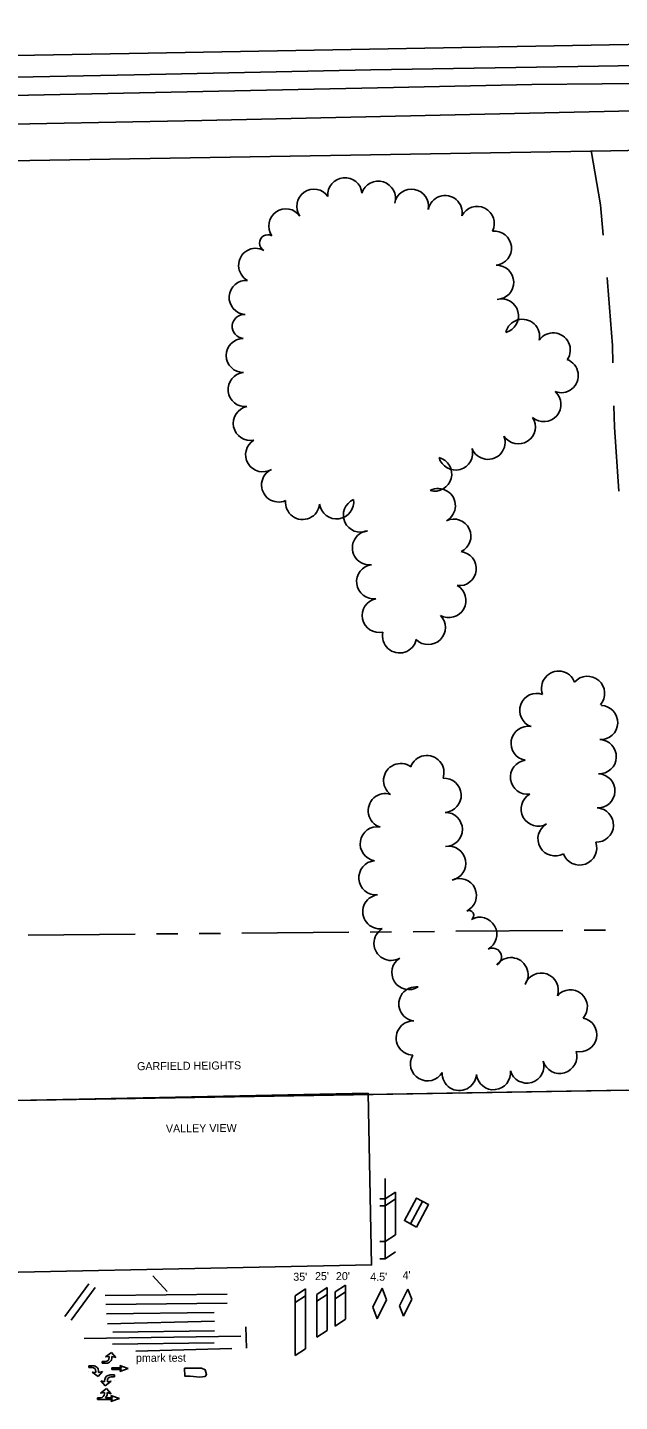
# Model space of a CAD drawing. Extents: x -2233 to 187241, y 4582 to 150524.
# Drawn here: x 103255 to 103601, y 58619 to 59422 of the extents above; entities that cross this region are included whole.
import ezdxf

# ---------------------------------------------------------------- set-up
doc = ezdxf.new("R2010")
doc.units = 0
for name, color, linetype in [('BLDG', 7, 'Continuous'), ('DIVISIONS', 7, 'Continuous'), ('DRIVWY', 7, 'Continuous'), ('DV_X_Corp_Line', 7, 'Continuous'), ('GE_X_CL_2000', 7, 'Continuous'), ('PM_P_Cells', 7, 'Continuous'), ('PM_P_Channelizing_Line', 7, 'Continuous'), ('PM_P_CL_Dashed', 7, 'Continuous'), ('PM_P_CL_Double_Solid', 7, 'Continuous'), ('PM_P_CL_Pass_Proh_Lt', 7, 'Continuous'), ('PM_P_CL_Pass_Proh_Rt', 7, 'Continuous'), ('PM_P_Crosswalk', 7, 'Continuous'), ('PM_P_Edge_Line', 7, 'Continuous'), ('PM_P_Island', 7, 'Continuous'), ('PM_P_Lane_Line', 7, 'Continuous'), ('PM_P_Stop_Line', 7, 'Continuous'), ('PM_P_Text', 7, 'Continuous'), ('PM_P_Transverse_Line', 7, 'Continuous'), ('ROAD', 7, 'Continuous'), ('RW_X_Fee_RW', 7, 'Continuous'), ('SG_P_Detection', 7, 'Continuous'), ('TREES', 7, 'Continuous')]:
    doc.layers.add(name, color=color, linetype=linetype)

msp = doc.modelspace()

# ---------------------------------------------------------------- linework, layer by layer
at = {"layer": 'BLDG'}
msp.add_lwpolyline([(103153.42, 58792.9), (103453.99, 58799.02), (103456.04, 58698.72), (103155.45, 58692.59)], close=True, dxfattribs=at)
at = {"layer": 'DIVISIONS'}
for p, q in [((103317.76, 58892.09), (103255.26, 58891.54)), ((103342.76, 58892.3), (103330.26, 58892.19)), ((103367.76, 58892.52), (103355.26, 58892.41)), ((103442.75, 58893.18), (103380.26, 58892.63)), ((103467.75, 58893.39), (103455.25, 58893.29)), ((103492.75, 58893.61), (103480.25, 58893.5)), ((103567.75, 58894.27), (103505.25, 58893.72)), ((103592.75, 58894.49), (103580.25, 58894.38))]:
    msp.add_line(p, q, dxfattribs=at)
at = {"layer": 'DRIVWY'}
for points in [[(103584.47, 59350.22), (103589.9, 59318.4), (103591.47, 59300.75)], [(103593.7, 59275.85), (103593.94, 59273.17), (103596.9, 59236.13), (103597.11, 59225.98)], [(103597.66, 59200.99), (103597.94, 59188.42), (103600.63, 59151.08)]]:
    msp.add_lwpolyline(points, dxfattribs=at)
at = {"layer": 'DV_X_Corp_Line'}
for p, q in [((103605.04, 58800.91), (103465.01, 58798.49)), ((103605.04, 58800.91), (103465.01, 58798.49)), ((103465.01, 58798.49), (103605.04, 58800.91)), ((103465.01, 58798.49), (103605.04, 58800.91)), ((103465.01, 58798.49), (103154.56, 58793.13)), ((103465.01, 58798.49), (103154.56, 58793.13)), ((103154.56, 58793.13), (103465.01, 58798.49)), ((103154.56, 58793.13), (103465.01, 58798.49))]:
    msp.add_line(p, q, dxfattribs=at)
at = {"layer": 'GE_X_CL_2000'}
msp.add_lwpolyline([(102704.74, 59370.41), (102779.38, 59373.19), (102838.08, 59373.89), (102907.65, 59375.38), (102983.02, 59376.9), (103072.7, 59378.69), (103137.57, 59379.6), (103218.01, 59381.7), (103468.94, 59386.95), (103549.74, 59388.86), (103632, 59389.52), (103699.21, 59391.17), (103769.33, 59392.48), (103834.92, 59393.77), (103889.81, 59394.62), (103960.32, 59395.62), (104026.62, 59396.95), (104110.49, 59398.48), (104164.38, 59399.57), (104188.68, 59400.08)], dxfattribs=at)
at = {"layer": 'PM_P_Cells'}
for p, q in [((103303.93, 58647.58), (103300.41, 58644.91)), ((103306.49, 58644.58), (103303.93, 58647.58)), ((103290.74, 58638.75), (103290.74, 58639.75)), ((103290.74, 58639.75), (103293.22, 58639.75)), ((103292.61, 58638.75), (103290.74, 58638.75)), ((103298.49, 58644.58), (103298.49, 58644.58)), ((103300.36, 58642.24), (103298.49, 58642.24)), ((103298.49, 58642.24), (103298.49, 58641.24)), ((103298.49, 58641.24), (103300.97, 58641.24)), ((103300.41, 58644.91), (103302.65, 58645.24)), ((103302.65, 58645.24), (103302.65, 58644.54)), ((103304.25, 58644.58), (103304.25, 58645.24)), ((103304.25, 58645.24), (103306.49, 58644.58)), ((103304.29, 58637.62), (103304.29, 58638.62)), ((103304.29, 58638.62), (103309.79, 58638.62)), ((103306.49, 58644.58), (103306.49, 58644.58)), ((103309.79, 58638.62), (103308.79, 58639.85)), ((103308.79, 58639.85), (103313.79, 58638.12)), ((103290.74, 58636.41), (103290.74, 58636.41)), ((103296.18, 58633.41), (103292.66, 58636.08)), ((103292.66, 58636.08), (103294.9, 58635.75)), ((103294.9, 58635.75), (103294.9, 58636.45)), ((103298.74, 58636.41), (103296.18, 58633.41)), ((103296.5, 58636.41), (103296.5, 58635.75)), ((103296.5, 58635.75), (103298.74, 58636.41)), ((103297.74, 58631.02), (103297.74, 58631.02)), ((103299.98, 58630.35), (103297.74, 58631.02)), ((103297.74, 58631.02), (103300.3, 58628.02)), ((103298.74, 58636.41), (103298.74, 58636.41)), ((103299.98, 58631.02), (103299.98, 58630.35)), ((103300.3, 58628.02), (103303.82, 58630.68)), ((103301.58, 58630.35), (103301.58, 58631.05)), ((103303.82, 58630.68), (103301.58, 58630.35)), ((103305.74, 58634.35), (103303.26, 58634.35)), ((103303.88, 58633.35), (103305.74, 58633.35)), ((103304.29, 58638.12), (103304.29, 58638.12)), ((103309.79, 58637.62), (103304.29, 58637.62)), ((103305.74, 58633.35), (103305.74, 58634.35)), ((103305.74, 58631.02), (103305.74, 58631.02)), ((103313.79, 58638.12), (103308.79, 58636.38)), ((103308.79, 58636.38), (103309.79, 58637.62)), ((103313.79, 58638.12), (103313.79, 58638.12)), ((103301.17, 58626.41), (103297.65, 58623.74)), ((103297.65, 58623.74), (103299.89, 58624.07)), ((103299.89, 58624.07), (103299.89, 58623.37)), ((103303.73, 58623.41), (103301.17, 58626.41)), ((103301.49, 58623.41), (103301.49, 58624.07)), ((103301.49, 58624.07), (103303.73, 58623.41)), ((103295.92, 58622.24), (103295.92, 58622.24)), ((103295.92, 58621.07), (103295.92, 58620.07)), ((103297.59, 58621.07), (103295.92, 58621.07)), ((103295.92, 58620.07), (103304.67, 58620.07)), ((103308.67, 58620.57), (103303.67, 58622.31)), ((103303.67, 58622.31), (103304.67, 58621.07)), ((103303.67, 58618.84), (103308.67, 58620.57)), ((103304.67, 58620.07), (103303.67, 58618.84)), ((103308.67, 58622.24), (103308.67, 58622.24))]:
    msp.add_line(p, q, dxfattribs=at)
msp.add_lwpolyline([(103304.67, 58621.07), (103300.56, 58621.07)], dxfattribs=at)
for centre, radius, start, end in [((103292.61, 58636.45), 2.3, 0, 90), ((103293.22, 58636.46), 3.28, 359.09151, 90), ((103300.36, 58644.54), 2.3, 270, 0), ((103300.97, 58644.52), 3.28, 270, 0.90849), ((103303.26, 58631.07), 3.28, 90, 180.90849), ((103303.88, 58631.05), 2.3, 90, 180), ((103297.59, 58623.37), 2.3, 270, 360), ((103298.21, 58623.36), 3.28, 315.95343, 0.90849)]:
    msp.add_arc(centre, radius, start, end, dxfattribs=at)
at = {"layer": 'PM_P_Channelizing_Line'}
msp.add_line((103300.25, 58680.78), (103371.67, 58681.57), dxfattribs=at)
at = {"layer": 'PM_P_CL_Dashed'}
msp.add_line((103288.03, 58655.71), (103379.64, 58657.04), dxfattribs=at)
at = {"layer": 'PM_P_CL_Double_Solid'}
msp.add_line((103300.78, 58675.46), (103371.67, 58676.26), dxfattribs=at)
at = {"layer": 'PM_P_CL_Pass_Proh_Lt'}
msp.add_line((103301.05, 58670.15), (103363.97, 58670.95), dxfattribs=at)
at = {"layer": 'PM_P_CL_Pass_Proh_Rt'}
msp.add_line((103301.58, 58664.3), (103364.24, 58665.9), dxfattribs=at)
at = {"layer": 'PM_P_Crosswalk'}
for p, q in [((103290.79, 58687.61), (103276.72, 58668.48)), ((103294.41, 58685.56), (103280.34, 58666.43))]:
    msp.add_line(p, q, dxfattribs=at)
at = {"layer": 'PM_P_Edge_Line'}
for p, q in [((103304.76, 58659.43), (103364.23, 58660.23)), ((103304.5, 58652.35), (103363.97, 58653.15))]:
    msp.add_line(p, q, dxfattribs=at)
at = {"layer": 'PM_P_Island'}
msp.add_lwpolyline([(103346.66, 58638.37), (103356.56, 58638.37), (103358.8, 58637.44), (103359.55, 58634.64), (103358.8, 58633.52), (103355.62, 58633.15), (103350.02, 58633.71), (103346.85, 58633.71)], close=True, dxfattribs=at)
at = {"layer": 'PM_P_Lane_Line'}
msp.add_line((103318.32, 58648.37), (103374.31, 58649.77), dxfattribs=at)
at = {"layer": 'PM_P_Stop_Line'}
msp.add_line((103382.83, 58649.96), (103382.56, 58662.44), dxfattribs=at)
at = {"layer": 'PM_P_Transverse_Line'}
msp.add_line((103328.18, 58692.29), (103336.63, 58683.15), dxfattribs=at)
at = {"layer": 'ROAD'}
msp.add_lwpolyline([(102571.34, 59379.86), (102730.39, 59381.47), (102909.35, 59384.67), (103042.82, 59388), (103189.02, 59391.81), (103317.24, 59394.44), (103455.61, 59397.39), (103588.59, 59399.56), (103829.5, 59403.66), (103951.38, 59407.88), (104068.97, 59408.97), (104193.45, 59411.28), (104193.86, 59383.93), (104083.75, 59383.64), (103867.89, 59379), (103661.45, 59374.58), (103356.74, 59367.7), (103074.88, 59362.33), (102737.13, 59355.63), (102571.99, 59353.73)], dxfattribs=at)
at = {"layer": 'RW_X_Fee_RW'}
msp.add_line((102806.64, 58787.13), (104461.34, 58815.68), dxfattribs=at)
for points in [[(103325.46, 59407.05), (103886.48, 59417.2), (104022.1, 59419.91), (104157.94, 59422.11)], [(102829.55, 59398.05), (102985.53, 59400.88), (103225.49, 59405.24), (103325.46, 59407.05)], [(102822.77, 59337.15), (103595.86, 59350.07), (103615.85, 59350.41), (103926.82, 59355.61), (104066.8, 59357.95), (104180.55, 59359.85)]]:
    msp.add_lwpolyline(points, dxfattribs=at)
at = {"layer": 'SG_P_Detection'}
for p, q in [((103463.97, 58702.32), (103463.97, 58749.19)), ((103463.97, 58737.32), (103460.83, 58737.32)), ((103469.97, 58741.32), (103463.97, 58737.32)), ((103463.97, 58737.32), (103463.97, 58712.32)), ((103469.97, 58737.32), (103463.97, 58733.32)), ((103469.97, 58716.32), (103469.97, 58741.32)), ((103485.87, 58735.85), (103478.69, 58722.68)), ((103463.97, 58733.32), (103460.83, 58733.32)), ((103463.97, 58712.32), (103460.83, 58712.32)), ((103469.97, 58716.32), (103463.97, 58712.32)), ((103469.96, 58706.32), (103463.96, 58702.32)), ((103463.97, 58702.32), (103460.83, 58702.32)), ((103440.74, 58686.92), (103434.74, 58682.92)), ((103440.74, 58666.92), (103440.74, 58686.92)), ((103417.32, 58684.68), (103411.32, 58680.68)), ((103411.32, 58680.68), (103411.32, 58645.68)), ((103417.32, 58680.68), (103411.32, 58676.68)), ((103417.32, 58649.68), (103417.32, 58684.68)), ((103424.05, 58681.42), (103424.04, 58656.42)), ((103430.05, 58685.42), (103424.05, 58681.42)), ((103430.05, 58681.42), (103424.05, 58677.42)), ((103430.04, 58660.42), (103430.05, 58685.42)), ((103434.74, 58662.92), (103434.74, 58682.92)), ((103440.74, 58682.92), (103434.74, 58678.92)), ((103456.75, 58674.03), (103462.13, 58685.03)), ((103462.13, 58685.03), (103464.7, 58678.26)), ((103472.41, 58674.82), (103477.19, 58684.6)), ((103477.19, 58684.6), (103479.47, 58678.58)), ((103459.32, 58667.25), (103456.75, 58674.03)), ((103464.7, 58678.26), (103459.32, 58667.25)), ((103474.69, 58668.8), (103472.41, 58674.82)), ((103479.47, 58678.58), (103474.69, 58668.8)), ((103440.74, 58666.92), (103434.74, 58662.92)), ((103430.04, 58660.42), (103424.04, 58656.42)), ((103417.32, 58649.68), (103411.32, 58645.68))]:
    msp.add_line(p, q, dxfattribs=at)
msp.add_lwpolyline([(103482.2, 58720.76), (103475.18, 58724.59), (103482.36, 58737.76), (103489.38, 58733.93)], close=True, dxfattribs=at)
at = {"layer": 'TREES'}
for centre, radius, start, end in [((103440.47, 59324.32), 10, 5.49848, 185.49848), ((103459.98, 59322.33), 10, 342.90311, 162.90311), ((103422.33, 59317.61), 10, 35.05898, 215.05898), ((103479.37, 59317.58), 10, 349.55995, 169.55995), ((103499.03, 59313.89), 10, 349.16952, 169.16952), ((103405.96, 59306.13), 10, 35.05898, 215.05898), ((103517.79, 59307.53), 10, 333.36783, 153.36783), ((103395.43, 59296.09), 4.89, 61.35504, 241.35504), ((103527.8, 59293.1), 10, 276.14039, 96.14039), ((103388.29, 59283.03), 10, 61.35504, 241.35504), ((103529.12, 59273.16), 10, 271.45495, 91.45495), ((103382.77, 59264.28), 10, 85.83432, 265.83432), ((103531.94, 59253.5), 10, 284.82692, 104.82692), ((103381.54, 59247.33), 6.99, 85.83432, 265.83432), ((103544.23, 59241.54), 10, 346.7093, 166.7093), ((103562.2, 59233.58), 10, 325.53236, 145.53236), ((103381.09, 59230.36), 10, 90.33871, 270.33871), ((103566.85, 59218.59), 10, 248.94024, 68.94024), ((103382.17, 59210.41), 10, 95.88993, 275.88993), ((103556.72, 59201.69), 10, 229.13189, 49.13189), ((103385.2, 59190.67), 10, 101.5568, 281.5568), ((103541.8, 59188.67), 10, 213.0732, 33.0732), ((103392.41, 59172.33), 10, 121.38015, 301.38015), ((103524.08, 59179.63), 10, 200.99677, 20.99677), ((103492.88, 59161.03), 10, 254.94306, 74.94306), ((103505.11, 59173.37), 10, 195.56326, 15.56326), ((103401.71, 59154.67), 10, 114.14206, 294.14206), ((103415.74, 59144.47), 10, 173.8355, 353.8355), ((103435.59, 59144.78), 10, 187.97016, 7.97016), ((103449.54, 59137.02), 10, 113.86041, 293.86041), ((103495.04, 59142.57), 10, 298.40783, 118.40783), ((103504.07, 59124.74), 10, 295.32533, 115.32533), ((103454.8, 59117.95), 10, 97.01798, 277.01798), ((103507.24, 59105.76), 10, 263.60396, 83.60396), ((103457.26, 59098.1), 10, 97.07153, 277.07153), ((103501.18, 59087.13), 10, 240.39443, 60.39443), ((103460.56, 59078.4), 10, 101.95995, 281.95995), ((103489.2, 59071.34), 10, 225.20014, 45.20014), ((103472.39, 59066.43), 10, 167.3763, 347.3763), ((103565.37, 59035.84), 10, 20.98684, 200.98684), ((103582.24, 59032.84), 10, 318.8924, 138.8924), ((103552.64, 59022.85), 10, 70.16436, 250.16436), ((103589.92, 59015.78), 10, 267.63983, 87.63983), ((103590.05, 59026.02), 0.373, 318.23992, 138.23992), ((103547.53, 59003.59), 10, 80.12219, 260.12219), ((103589.1, 58995.8), 10, 267.63983, 87.63983), ((103488.36, 58986.56), 10, 340.5029, 160.5029), ((103547.17, 58983.83), 10, 97.81099, 277.81099), ((103473.03, 58981.83), 10, 53.80129, 233.80129), ((103588.27, 58975.82), 10, 267.63983, 87.63983), ((103498.41, 58973.24), 10, 273.55165, 93.55165), ((103464.04, 58964.24), 10, 72.05099, 252.05099), ((103553.42, 58965.2), 10, 119.28615, 299.28615), ((103499.11, 58953.26), 10, 270.47023, 90.47022), ((103587.45, 58955.83), 10, 267.63983, 87.63983), ((103459.34, 58944.86), 10, 80.69099, 260.69099), ((103563.26, 58947.79), 10, 119.64053, 299.64053), ((103577.62, 58942.47), 10, 199.70339, 19.70339), ((103501.12, 58933.45), 10, 281.11554, 101.11554), ((103458.59, 58925.03), 10, 94.97283, 274.97283), ((103507.33, 58914.6), 10, 295.38507, 115.38507), ((103460.88, 58905.17), 10, 98.19724, 278.19724), ((103512.99, 58903.13), 2.79, 299.26018, 119.26018), ((103519.24, 58891.97), 10, 299.26018, 119.26018), ((103467.42, 58886.68), 10, 120.72536, 300.72536), ((103526.71, 58878.64), 5.28, 299.26018, 119.26018), ((103477.87, 58869.63), 10, 122.31563, 302.31563), ((103537.51, 58868.35), 10, 325.33027, 145.33027), ((103555.18, 58859.37), 10, 340.75966, 160.75966), ((103481.95, 58851.26), 10, 82.69934, 262.69934), ((103572.2, 58849.55), 10, 319.27364, 139.27364), ((103480.4, 58831.35), 10, 88.4157, 268.4157), ((103577.68, 58833.24), 10, 257.92351, 77.92351), ((103566, 58820.62), 10, 196.50893, 16.50893), ((103488.75, 58816.28), 10, 149.56299, 329.56299), ((103546.81, 58814.98), 10, 196.28455, 16.28455), ((103507.35, 58810.62), 10, 176.5659, 356.5659), ((103527.27, 58811.1), 10, 186.17813, 6.17813)]:
    msp.add_arc(centre, radius, start, end, dxfattribs=at)

# ---------------------------------------------------------------- texts
at = {"layer": 'DIVISIONS'}
for s, p in [('GARFIELD HEIGHTS', (103318.96, 58812.52)), ('VALLEY VIEW', (103335.82, 58776.09))]:
    msp.add_text(s, height=4.68, rotation=0.5, dxfattribs=at).set_placement(p)
at = {"layer": 'PM_P_Text'}
for s, p in [("4'", (103474.17, 58690.35)), ("35'", (103410.26, 58689.42)), ("25'", (103422.96, 58689.79)), ("20'", (103435.2, 58689.79)), ("4.5'", (103455.24, 58689.42)), ('pmark test', (103318.31, 58641.99))]:
    msp.add_text(s, height=4.68, rotation=0.25, dxfattribs=at).set_placement(p)

doc.saveas('drawing.dxf')
